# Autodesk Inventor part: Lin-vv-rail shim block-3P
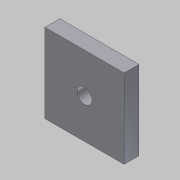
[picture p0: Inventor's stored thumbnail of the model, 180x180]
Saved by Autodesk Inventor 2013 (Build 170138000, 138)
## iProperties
Created: 2012-05
Part Number: Lin-vv-rail shim block-3P
Material: Stainless Steel
Document SubType Name: Modeling
Designer: ssc
Mass: 61.9183 g
Surface Area: 35.8706 cm^2
Volume: 7.66316 cm^3
Density: 8.08 g/cm^3
Author: ssc
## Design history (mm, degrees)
sketch "Sketch1"
  geometry: L1 (0, 0)-(25.4, 0); L2 (25.4, 0)-(25.4, 50.8); L3 (25.4, 50.8)-(0, 50.8); L4 (0, 50.8)-(0, 0)
  constraints: 8 end point, 2 parallel, 1 horizontal, 1 perpendicular, 1 other
  dimensions: "d0" = 50.8 distance of L3.end L1.start; "d1" = 25.4 distance of L1.start L1.end
extrude "Extrusion1" new body sketch "Sketch1" distance "d2" = 6.35; taper "d3" = 0 deg
hole "Hole1" diameter "d6" = 10.3124; stored, may be unused: countersink angle "d10" = 82 deg, drill point angle "d12" = 118 deg; dims "d4" = 25.4, "d5" = 12.7, "d7" = 12.7, "d8" = 9.525, "d9" = 6.35, "d11" = 19.05
body "Solid1"
